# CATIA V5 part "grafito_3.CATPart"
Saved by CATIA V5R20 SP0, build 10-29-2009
Part number: grafito_3
Revision: ANY
Definition: UNKNOWN
Nomenclature: grafito
Source: Unknown
Bounding box of the stored display mesh (mm): x -2.498 to 2.498, y 1.55 to 21.547, z -2.5 to 2.5
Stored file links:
  C:\Users\Utente\Desktop\IO LAVORO\3D X SITO CF\CUMSA\3D files SD\SD 4528\grafito_3.CATPart
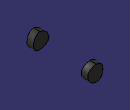
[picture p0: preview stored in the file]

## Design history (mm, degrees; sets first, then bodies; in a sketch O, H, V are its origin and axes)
Body1 "Saliente-Extruir1" (main body)
  Solid1: solid without history
Body2 "Saliente-Extruir1"
  Solid2: solid without history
